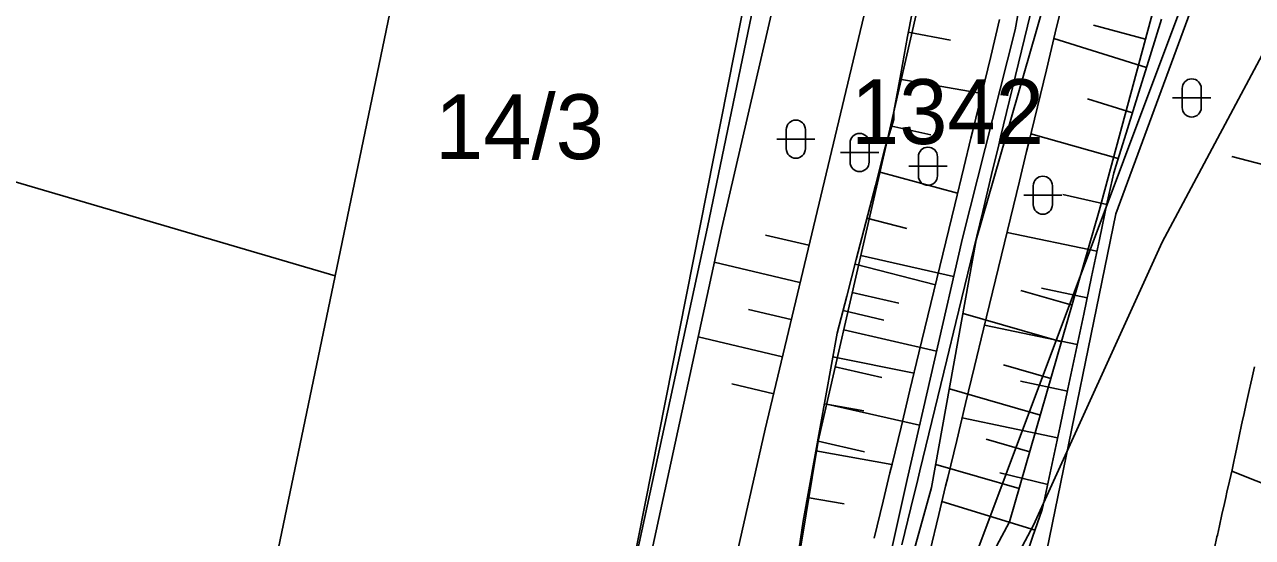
# Model space of a CAD drawing. Extents: x -564037 to -563722, y -1163561 to -1163412.
# Drawn here: x -564009.62 to -563977.45, y -1163488.13 to -1163474.68 of the extents above; entities that cross this region are included whole.
import ezdxf

# ---------------------------------------------------------------- set-up
doc = ezdxf.new("R2010")
doc.units = 0
for name, color, linetype in [('5', 7, 'Continuous'), ('Definiční bod kú', 7, 'Continuous'), ('Hranice parcel', 7, 'Continuous'), ('Line', 7, 'Continuous'), ('Parcelní čísla', 7, 'Continuous'), ('Vrstva 14', 7, 'Continuous'), ('Vrstva 25', 7, 'Continuous'), ('Vrstva 48', 7, 'Continuous')]:
    doc.layers.add(name, color=color, linetype=linetype)

msp = doc.modelspace()

# ---------------------------------------------------------------- linework, layer by layer
for points in [[(-563982.839, -1163488.47), (-563983.409, -1163491.846), (-563990.891, -1163500.051), (-563993.495, -1163501.54), (-564001.695, -1163505.76), (-564021.072, -1163514.028), (-564021.939, -1163519.359), (-564028.021, -1163535.92), (-563982.332, -1163543.556), (-563870.708, -1163549.442), (-563829.278, -1163493.346), (-563857.264, -1163473.56), (-563873.956, -1163464.96), (-563885.354, -1163462.845), (-563964.187, -1163417.135), (-563977.612, -1163460.096), (-563977.509, -1163470.055), (-563981.031, -1163479.642), (-563982.839, -1163488.47)], [(-563985.2, -1163468.42), (-563986.491, -1163474.99), (-563986.67, -1163475.976), (-563986.847, -1163476.962), (-563986.852, -1163477.171), (-563987.082, -1163477.934), (-563987.332, -1163478.902), (-563987.582, -1163479.87), (-563987.832, -1163480.839), (-563988.082, -1163481.807), (-563988.332, -1163482.775), (-563989.228, -1163487.703), (-563989.63, -1163490.42), (-563990.74, -1163493.02), (-563991.383, -1163493.786), (-563992.027, -1163494.551), (-563992.803, -1163495.487), (-563991.13, -1163497.04), (-563989.264, -1163498.329)], [(-563983.113, -1163473.749), (-563983.348, -1163474.721), (-563983.583, -1163475.693), (-563983.818, -1163476.665), (-563984.052, -1163477.637), (-563984.101, -1163477.836), (-563984.287, -1163478.609), (-563984.522, -1163479.581), (-563984.757, -1163480.553), (-563984.992, -1163481.525), (-563985.227, -1163482.497), (-563985.462, -1163483.469), (-563985.697, -1163484.441), (-563985.932, -1163485.413), (-563986.167, -1163486.385), (-563986.222, -1163486.612), (-563986.402, -1163487.357), (-563986.637, -1163488.329)], [(-563982.384, -1163473.925), (-563982.619, -1163474.897), (-563982.854, -1163475.869), (-563983.089, -1163476.841), (-563983.323, -1163477.813), (-563983.372, -1163478.013), (-563983.558, -1163478.785), (-563983.793, -1163479.757), (-563984.028, -1163480.729), (-563984.263, -1163481.701), (-563984.498, -1163482.673), (-563984.733, -1163483.645), (-563984.968, -1163484.617), (-563985.203, -1163485.589), (-563985.438, -1163486.561), (-563985.493, -1163486.788), (-563985.673, -1163487.533), (-563985.908, -1163488.505)], [(-563984.077, -1163474.545), (-563984.312, -1163475.517), (-563984.547, -1163476.489), (-563984.781, -1163477.461), (-563984.83, -1163477.66), (-563985.016, -1163478.433), (-563985.251, -1163479.405), (-563985.486, -1163480.377), (-563985.721, -1163481.349), (-563985.956, -1163482.321), (-563986.191, -1163483.293), (-563986.426, -1163484.265), (-563986.661, -1163485.237), (-563986.896, -1163486.209), (-563986.951, -1163486.436), (-563987.131, -1163487.181), (-563987.366, -1163488.153)], [(-563979.835, -1163474.542), (-563980.132, -1163475.498), (-563980.429, -1163476.455), (-563980.727, -1163477.412), (-563981.024, -1163478.369), (-563981.085, -1163478.565), (-563981.259, -1163479.341), (-563981.463, -1163480.321), (-563981.669, -1163481.3), (-563981.876, -1163482.279), (-563982.082, -1163483.258), (-563982.288, -1163484.237), (-563982.494, -1163485.216), (-563982.7, -1163486.194), (-563982.907, -1163487.173), (-563982.96, -1163487.4), (-563983.215, -1163488.128), (-563983.539, -1163489.078)], [(-563978.449, -1163488.413), (-563978.384, -1163488.119), (-563978.374, -1163488.072), (-563978.319, -1163487.825), (-563978.253, -1163487.532), (-563978.187, -1163487.238), (-563978.152, -1163487.083), (-563978.121, -1163486.945), (-563978.054, -1163486.652), (-563977.986, -1163486.359), (-563977.93, -1163486.095), (-563977.923, -1163486.065), (-563977.862, -1163485.77), (-563977.8, -1163485.475), (-563977.737, -1163485.18), (-563977.72, -1163485.101), (-563977.674, -1163484.885), (-563977.619, -1163484.629), (-563977.611, -1163484.589), (-563977.542, -1163484.279), (-563977.498, -1163484.081), (-563977.473, -1163483.969), (-563977.402, -1163483.659)], [(-563978.449, -1163488.413), (-563978.384, -1163488.119), (-563978.374, -1163488.072), (-563978.319, -1163487.825), (-563978.253, -1163487.532), (-563978.187, -1163487.238), (-563978.152, -1163487.083), (-563978.121, -1163486.945), (-563978.054, -1163486.652), (-563977.986, -1163486.359), (-563977.93, -1163486.095), (-563977.923, -1163486.065), (-563977.862, -1163485.77), (-563977.8, -1163485.475), (-563977.737, -1163485.18), (-563977.72, -1163485.101), (-563977.674, -1163484.885), (-563977.619, -1163484.629), (-563977.611, -1163484.589), (-563977.542, -1163484.279), (-563977.498, -1163484.081), (-563977.473, -1163483.969), (-563977.402, -1163483.659)]]:
    msp.add_lwpolyline(points)
at = {"layer": '5'}
msp.add_line((-563977.993, -1163478.142), (-563940.586, -1163487.812), dxfattribs=at)
at = {"layer": 'Definiční bod kú'}
msp.add_lwpolyline([(-564036.505, -1163529.976), (-564035.88, -1163528.59), (-564032.62, -1163523.46), (-564027.5, -1163518.53), (-564023.88, -1163515.79), (-564019.18, -1163512.89), (-564014.48, -1163510.5), (-564004.65, -1163507.04), (-563996.46, -1163502.51), (-563993.72, -1163500.97), (-563990.58, -1163498.69), (-563987.18, -1163495.32), (-563983.19, -1163487.81), (-563979.82, -1163480.39), (-563975.55, -1163472.37), (-563971.76, -1163466.68), (-563970.57, -1163458.32), (-563969.42, -1163449.87), (-563967.93, -1163441.99), (-563966.12, -1163434.66), (-563963.95, -1163427.04), (-563963.19, -1163422.98), (-563961.48, -1163418.93), (-563957.126, -1163412.494)], dxfattribs=at)
at = {"layer": 'Hranice parcel'}
for p, q in [((-564001.49, -1163481.27), (-563996.99, -1163459.6)), ((-564003.59, -1163491.36), (-564001.49, -1163481.27))]:
    msp.add_line(p, q, dxfattribs=at)
for points in [[(-563978.16, -1163460.35), (-563977.81, -1163470.18), (-563986.9, -1163494.46), (-563994.41, -1163501.54), (-564003.29, -1163506.07), (-564021.9, -1163513.74)], [(-564003.59, -1163491.36), (-563994.27, -1163491.83), (-563988.32, -1163461.72)], [(-564036.505, -1163475.472), (-564029.42, -1163475.59), (-564022.66, -1163475.05), (-564001.49, -1163481.27)]]:
    msp.add_lwpolyline(points, dxfattribs=at)
at = {"layer": 'Line'}
for p, q in [((-563985.365, -1163475.094), (-563986.47, -1163474.884)), ((-563980.227, -1163475.803), (-563982.655, -1163475.049)), ((-563986.695, -1163476.114), (-563984.547, -1163476.492)), ((-563981.774, -1163476.632), (-563980.598, -1163476.997)), ((-563985.883, -1163477.571), (-563986.903, -1163477.342)), ((-563980.969, -1163478.191), (-563983.259, -1163477.549)), ((-563987.241, -1163478.546), (-563985.178, -1163479.101)), ((-563982.426, -1163479.138), (-563981.272, -1163479.402)), ((-563986.51, -1163480.025), (-563987.553, -1163479.756)), ((-563981.527, -1163480.626), (-563983.884, -1163480.132)), ((-563987.865, -1163480.966), (-563985.76, -1163481.51)), ((-563982.981, -1163481.597), (-563981.785, -1163481.849)), ((-563987.111, -1163482.431), (-563988.178, -1163482.177)), ((-563982.043, -1163483.072), (-563984.471, -1163482.561)), ((-563988.445, -1163483.397), (-563986.319, -1163483.823)), ((-563983.533, -1163484.036), (-563982.3, -1163484.296)), ((-563987.637, -1163484.814), (-563988.669, -1163484.627)), ((-563982.558, -1163485.519), (-563985.059, -1163484.992)), ((-563988.892, -1163485.857), (-563986.899, -1163486.219)), ((-563984.074, -1163486.434), (-563982.816, -1163486.742)), ((-563974.19, -1163487.923), (-563977.994, -1163486.392)), ((-563988.153, -1163487.253), (-563989.116, -1163487.087)), ((-563983.151, -1163487.944), (-563985.589, -1163487.187))]:
    msp.add_line(p, q, dxfattribs=at)
at = {"layer": 'Vrstva 14'}
for points in [[(-564018.41, -1163451.2), (-564015.23, -1163452.19), (-564012.52, -1163453.4), (-564007.28, -1163455.88), (-563999.25, -1163459.72), (-563994.12, -1163462.21), (-563988.58, -1163464.9), (-563990.48, -1163473.96), (-563991.73, -1163479.99), (-563994.29, -1163491.84), (-564004.63, -1163491.62)], [(-563978.09, -1163460.32), (-563977.36, -1163462.71), (-563977.84, -1163465.15), (-563976.09, -1163465.55), (-563974.34, -1163466.75), (-563974.1, -1163467.69), (-563974.4, -1163469.44), (-563976.73, -1163469.93), (-563977.88, -1163469.51), (-563978.75, -1163470.09), (-563979.22, -1163471.2), (-563981.47, -1163479.57), (-563983.82, -1163487.72), (-563987.7, -1163494.99), (-563990.79, -1163498.34), (-563994.06, -1163500.55), (-563996.65, -1163502.12), (-564005.13, -1163506.34), (-564014.58, -1163510.01)], [(-563994.12, -1163462.21), (-563988.34, -1163464.58), (-563987.88, -1163465.6), (-563989.98, -1163474.05), (-563991.36, -1163480.01), (-563993.23, -1163488.68), (-563992.87, -1163489.46), (-563993.2, -1163491.27), (-563993.97, -1163492.39), (-563995.48, -1163492.66)], [(-563987.78, -1163463.99), (-563986.5, -1163465.86), (-563986.56, -1163468.15), (-563987.54, -1163474.06), (-563990.22, -1163485.29), (-563991.34, -1163490.23), (-563992.03, -1163492.59), (-563994.18, -1163495.16)], [(-563991.13, -1163497.04), (-563989.1, -1163494.14), (-563987.28, -1163490.12), (-563986.5, -1163486.61), (-563985.05, -1163480.28), (-563983.67, -1163474.82), (-563982.48, -1163468.18)], [(-563993.16, -1163495.9), (-563990.74, -1163493.02), (-563989.63, -1163490.42), (-563988.83, -1163485.61), (-563986.26, -1163474.42), (-563985.2, -1163468.42)], [(-563981.34, -1163468.6), (-563983.12, -1163474.86), (-563984.69, -1163480.33), (-563985.86, -1163486.82), (-563986.85, -1163490.38), (-563988.78, -1163494.16), (-563991.13, -1163497.04)]]:
    msp.add_lwpolyline(points, dxfattribs=at)
at = {"layer": 'Vrstva 25'}
for p, q in [((-563979.546, -1163476.606), (-563978.546, -1163476.606)), ((-563979.296, -1163476.356), (-563979.296, -1163476.856)), ((-563978.796, -1163476.356), (-563978.796, -1163476.856)), ((-563989.666, -1163477.436), (-563989.666, -1163477.936)), ((-563989.166, -1163477.436), (-563989.166, -1163477.936)), ((-563989.916, -1163477.686), (-563988.916, -1163477.686)), ((-563987.996, -1163477.786), (-563987.996, -1163478.286)), ((-563987.496, -1163477.786), (-563987.496, -1163478.286)), ((-563988.246, -1163478.036), (-563987.246, -1163478.036)), ((-563986.206, -1163478.146), (-563986.206, -1163478.646)), ((-563985.706, -1163478.146), (-563985.706, -1163478.646)), ((-563986.456, -1163478.396), (-563985.456, -1163478.396)), ((-563983.446, -1163479.156), (-563982.446, -1163479.156)), ((-563983.196, -1163478.906), (-563983.196, -1163479.406)), ((-563982.696, -1163478.906), (-563982.696, -1163479.406))]:
    msp.add_line(p, q, dxfattribs=at)
for centre, start, end in [((-563979.046, -1163476.356), 0, 180), ((-563979.046, -1163476.856), 180, 0), ((-563989.416, -1163477.436), 0, 180), ((-563987.746, -1163477.786), 0, 180), ((-563985.956, -1163478.146), 0, 180), ((-563989.416, -1163477.936), 180, 0), ((-563987.746, -1163478.286), 180, 0), ((-563985.956, -1163478.646), 180, 0), ((-563982.946, -1163478.906), 0, 180), ((-563982.946, -1163479.406), 180, 0)]:
    msp.add_arc(centre, 0.25, start, end, dxfattribs=at)
at = {"layer": 'Vrstva 48'}
for p, q in [((-563980.253, -1163475.064), (-563981.616, -1163474.7)), ((-563989.08, -1163480.47), (-563990.213, -1163480.204)), ((-563987.716, -1163480.736), (-563985.282, -1163481.292)), ((-563989.308, -1163481.444), (-563991.558, -1163480.916)), ((-563987.939, -1163481.711), (-563986.722, -1163481.989)), ((-563982.18, -1163482.04), (-563983.519, -1163481.654)), ((-563989.536, -1163482.417), (-563990.653, -1163482.156)), ((-563982.457, -1163483.001), (-563985.037, -1163482.257)), ((-563988.161, -1163482.685), (-563985.728, -1163483.242)), ((-563989.764, -1163483.391), (-563991.98, -1163482.872)), ((-563988.384, -1163483.66), (-563987.168, -1163483.938)), ((-563982.734, -1163483.962), (-563983.975, -1163483.604)), ((-563989.993, -1163484.365), (-563991.092, -1163484.107)), ((-563983.011, -1163484.922), (-563985.394, -1163484.235)), ((-563988.607, -1163484.635), (-563986.175, -1163485.191)), ((-563988.83, -1163485.61), (-563987.614, -1163485.888)), ((-563983.289, -1163485.883), (-563984.431, -1163485.554)), ((-563983.566, -1163486.844), (-563985.751, -1163486.214))]:
    msp.add_line(p, q, dxfattribs=at)

# ---------------------------------------------------------------- texts
at = {"layer": 'Parcelní čísla'}
for s, p in [('1342', (-563987.974, -1163477.814)), ('14/3', (-563998.869, -1163478.21))]:
    msp.add_text(s, height=1.7, dxfattribs=at).set_placement(p)

doc.saveas('drawing.dxf')
